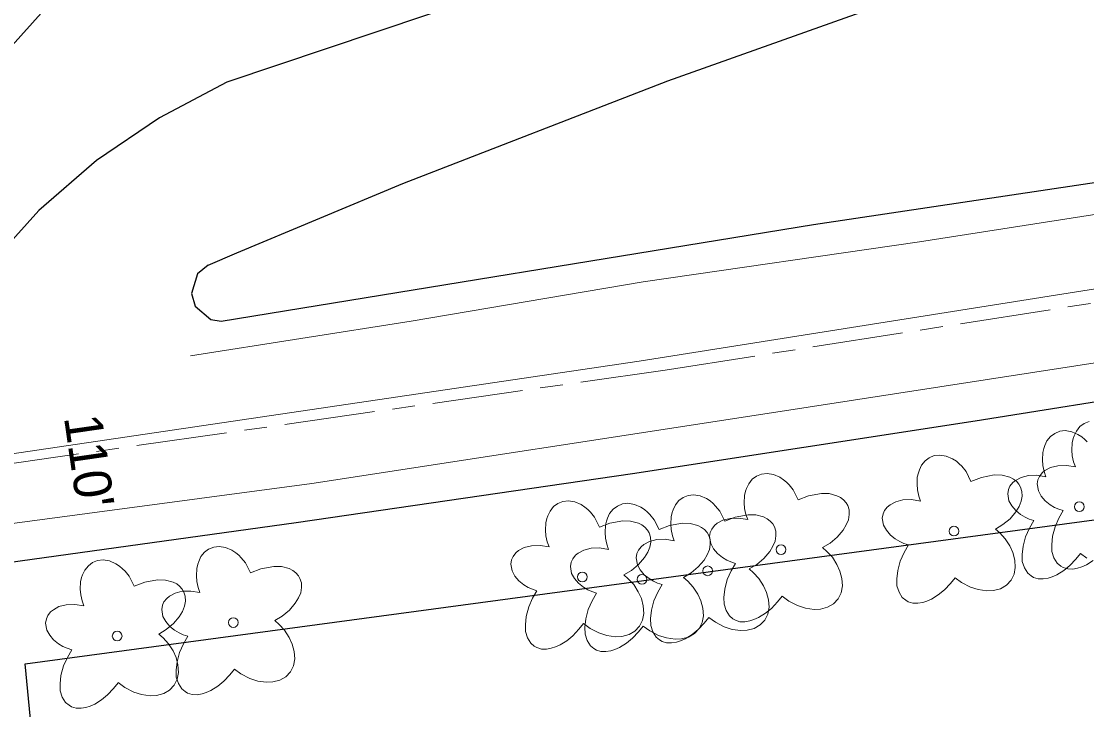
# Model space of a CAD drawing. Extents: x -861682 to -858969, y -1797841 to -1795153.
# Drawn here: x -859343 to -859173.6, y -1796475.1 to -1796365.6 of the extents above; entities that cross this region are included whole.
import ezdxf

# ---------------------------------------------------------------- set-up
doc = ezdxf.new("R2010")
doc.units = 0
doc.header["$LTSCALE"] = 2.4
doc.linetypes.add('LONG_DASH_SHORT_DASH', pattern=[9.9, 6, -1.2, 1.5, -1.2])
for name, color, linetype, lineweight in [('10', 7, 'Continuous', 25), ('17', 7, 'Continuous', 13), ('18', 7, 'Continuous', 13), ('32', 7, 'LONG_DASH_SHORT_DASH', 13), ('42', 7, 'Continuous', 25), ('54', 7, 'Continuous', 13)]:
    doc.layers.add(name, color=color, linetype=linetype, lineweight=lineweight)
doc.layers.add('43', color=7, linetype='Continuous')

msp = doc.modelspace()

# ---------------------------------------------------------------- linework, layer by layer
at = {"layer": '10'}
for points in [[(-859194.317, -1796336.227), (-859199.045, -1796337.856), (-859206.902, -1796340.557), (-859310.306, -1796375.338)], [(-859313.301, -1796404.44), (-859308.712, -1796402.455), (-859282.34, -1796391.428), (-859240.21, -1796375.108), (-859208.017, -1796363.681), (-859179.756, -1796354.374)], [(-859311.205, -1796413.342), (-859217.078, -1796397.962), (-859001.666, -1796365.735)], [(-859310.306, -1796375.338), (-859321.024, -1796380.988), (-859331.034, -1796387.814), (-859340.207, -1796395.728), (-859349.998, -1796406.585), (-859352.992, -1796410.59)], [(-859313.301, -1796404.44), (-859314.993, -1796405.821), (-859315.943, -1796408.916), (-859315.339, -1796410.971), (-859312.867, -1796413.061), (-859311.205, -1796413.342)], [(-859407.383, -1796460.011), (-859360.399, -1796453.848), (-859299.271, -1796445.38), (-859245.842, -1796437.563), (-859191.381, -1796429.192), (-859160.781, -1796424.311), (-859155.845, -1796423.511)]]:
    msp.add_lwpolyline(points, dxfattribs=at)
at = {"layer": '17'}
for points in [[(-859173.538, -1796432.552), (-859173.95, -1796432.15), (-859174.414, -1796431.75), (-859175.016, -1796431.358), (-859176.02, -1796430.926), (-859177.034, -1796430.756), (-859177.922, -1796430.856), (-859178.722, -1796431.19), (-859179.388, -1796431.676), (-859179.948, -1796432.382), (-859180.298, -1796433.138), (-859180.456, -1796433.576), (-859180.624, -1796434.252), (-859180.676, -1796435.414), (-859180.604, -1796436.312), (-859180.392, -1796437.274), (-859180.108, -1796438.08), (-859181.55, -1796437.848), (-859182.908, -1796437.898), (-859184.066, -1796438.184), (-859184.954, -1796438.682), (-859185.394, -1796439.026), (-859185.828, -1796439.592), (-859186.066, -1796440.126), (-859186.19, -1796440.804), (-859185.988, -1796441.908), (-859185.532, -1796442.72), (-859184.908, -1796443.482), (-859184.13, -1796444.098), (-859183.432, -1796444.522), (-859182.768, -1796444.81), (-859182.04, -1796445.048), (-859182.724, -1796446.26), (-859183.346, -1796447.628), (-859183.742, -1796449.13), (-859183.876, -1796450.464), (-859183.866, -1796451.554), (-859183.532, -1796452.572), (-859183.01, -1796453.418), (-859182.452, -1796453.854), (-859182.066, -1796454.1), (-859181.332, -1796454.324), (-859180.538, -1796454.336), (-859179.768, -1796454.212), (-859179.108, -1796454), (-859178.364, -1796453.678), (-859177.288, -1796452.998), (-859176.326, -1796452.212), (-859175.37, -1796451.194), (-859174.624, -1796450.284)], [(-859173.239, -1796429.289), (-859174.039, -1796429.623), (-859174.705, -1796430.109), (-859175.265, -1796430.815), (-859175.615, -1796431.571), (-859175.773, -1796432.009), (-859175.941, -1796432.685), (-859175.993, -1796433.847), (-859175.921, -1796434.745), (-859175.709, -1796435.707), (-859175.425, -1796436.513), (-859176.867, -1796436.281), (-859178.225, -1796436.331), (-859179.383, -1796436.617), (-859180.271, -1796437.115), (-859180.711, -1796437.459), (-859181.145, -1796438.025), (-859181.383, -1796438.559), (-859181.507, -1796439.237), (-859181.305, -1796440.341), (-859180.849, -1796441.153), (-859180.225, -1796441.915), (-859179.447, -1796442.531), (-859178.749, -1796442.955), (-859178.085, -1796443.243), (-859177.357, -1796443.481), (-859178.041, -1796444.693), (-859178.663, -1796446.061), (-859179.059, -1796447.563), (-859179.193, -1796448.897), (-859179.183, -1796449.987), (-859178.849, -1796451.005), (-859178.327, -1796451.851), (-859177.769, -1796452.287), (-859177.383, -1796452.533), (-859176.649, -1796452.757), (-859175.855, -1796452.769), (-859175.085, -1796452.645), (-859174.425, -1796452.433), (-859173.681, -1796452.111), (-859172.605, -1796451.431)], [(-859194.557, -1796454.151), (-859193.515, -1796454.919), (-859192.109, -1796455.641), (-859190.861, -1796456.047), (-859189.489, -1796456.243), (-859188.471, -1796456.193), (-859187.327, -1796455.903), (-859186.395, -1796455.351), (-859185.655, -1796454.563), (-859185.187, -1796453.605), (-859184.977, -1796452.527), (-859185.081, -1796451.331), (-859185.371, -1796450.159), (-859185.857, -1796449.099), (-859186.579, -1796447.955), (-859187.445, -1796447.035), (-859188.127, -1796446.423), (-859186.945, -1796445.707), (-859185.799, -1796444.759), (-859184.879, -1796443.667), (-859184.357, -1796442.811), (-859184.025, -1796441.997), (-859183.879, -1796441.181), (-859183.919, -1796440.419), (-859184.135, -1796439.739), (-859184.393, -1796439.287), (-859184.813, -1796438.813), (-859185.273, -1796438.459), (-859185.839, -1796438.169), (-859187.075, -1796437.841), (-859188.317, -1796437.807), (-859190.363, -1796438.183), (-859192.023, -1796438.821), (-859192.813, -1796437.243), (-859193.467, -1796436.429), (-859193.879, -1796436.027), (-859194.343, -1796435.627), (-859194.945, -1796435.235), (-859195.949, -1796434.803), (-859196.963, -1796434.633), (-859197.851, -1796434.733), (-859198.651, -1796435.067), (-859199.317, -1796435.553), (-859199.877, -1796436.259), (-859200.227, -1796437.015), (-859200.385, -1796437.453), (-859200.553, -1796438.129), (-859200.605, -1796439.291), (-859200.533, -1796440.189), (-859200.321, -1796441.151), (-859200.037, -1796441.957), (-859201.479, -1796441.725), (-859202.837, -1796441.775), (-859203.995, -1796442.061), (-859204.883, -1796442.559), (-859205.323, -1796442.903), (-859205.757, -1796443.469), (-859205.995, -1796444.003), (-859206.119, -1796444.681), (-859205.917, -1796445.785), (-859205.461, -1796446.597), (-859204.837, -1796447.359), (-859204.059, -1796447.975), (-859203.361, -1796448.399), (-859202.697, -1796448.687), (-859201.969, -1796448.925), (-859202.653, -1796450.137), (-859203.275, -1796451.505), (-859203.671, -1796453.007), (-859203.805, -1796454.341), (-859203.795, -1796455.431), (-859203.461, -1796456.449), (-859202.939, -1796457.295), (-859202.381, -1796457.731), (-859201.995, -1796457.977), (-859201.261, -1796458.201), (-859200.467, -1796458.213), (-859199.697, -1796458.089), (-859199.037, -1796457.877), (-859198.293, -1796457.555), (-859197.217, -1796456.875), (-859196.255, -1796456.089), (-859195.299, -1796455.071), (-859194.553, -1796454.161)], [(-859222.041, -1796457.089), (-859220.999, -1796457.857), (-859219.593, -1796458.579), (-859218.345, -1796458.985), (-859216.973, -1796459.181), (-859215.955, -1796459.131), (-859214.811, -1796458.841), (-859213.879, -1796458.289), (-859213.139, -1796457.501), (-859212.671, -1796456.543), (-859212.461, -1796455.465), (-859212.565, -1796454.269), (-859212.855, -1796453.097), (-859213.341, -1796452.037), (-859214.063, -1796450.893), (-859214.929, -1796449.973), (-859215.611, -1796449.361), (-859214.429, -1796448.645), (-859213.283, -1796447.697), (-859212.363, -1796446.605), (-859211.841, -1796445.749), (-859211.509, -1796444.935), (-859211.363, -1796444.119), (-859211.403, -1796443.357), (-859211.619, -1796442.677), (-859211.877, -1796442.225), (-859212.297, -1796441.751), (-859212.757, -1796441.397), (-859213.323, -1796441.107), (-859214.559, -1796440.779), (-859215.801, -1796440.745), (-859217.847, -1796441.121), (-859219.507, -1796441.759), (-859220.297, -1796440.181), (-859220.951, -1796439.367), (-859221.363, -1796438.965), (-859221.827, -1796438.565), (-859222.429, -1796438.173), (-859223.433, -1796437.741), (-859224.447, -1796437.571), (-859225.335, -1796437.671), (-859226.135, -1796438.005), (-859226.801, -1796438.491), (-859227.361, -1796439.197), (-859227.711, -1796439.953), (-859227.869, -1796440.391), (-859228.037, -1796441.067), (-859228.089, -1796442.229), (-859228.017, -1796443.127), (-859227.805, -1796444.089), (-859227.521, -1796444.895), (-859228.963, -1796444.663), (-859230.321, -1796444.713), (-859231.479, -1796444.999), (-859232.367, -1796445.497), (-859232.807, -1796445.841), (-859233.241, -1796446.407), (-859233.479, -1796446.941), (-859233.603, -1796447.619), (-859233.401, -1796448.723), (-859232.945, -1796449.535), (-859232.321, -1796450.297), (-859231.543, -1796450.913), (-859230.845, -1796451.337), (-859230.181, -1796451.625), (-859229.453, -1796451.863), (-859230.137, -1796453.075), (-859230.759, -1796454.443), (-859231.155, -1796455.945), (-859231.289, -1796457.279), (-859231.279, -1796458.369), (-859230.945, -1796459.387), (-859230.423, -1796460.233), (-859229.865, -1796460.669), (-859229.479, -1796460.915), (-859228.745, -1796461.139), (-859227.951, -1796461.151), (-859227.181, -1796461.027), (-859226.521, -1796460.815), (-859225.777, -1796460.493), (-859224.701, -1796459.813), (-859223.739, -1796459.027), (-859222.783, -1796458.009), (-859222.037, -1796457.099)], [(-859233.7, -1796460.467), (-859232.658, -1796461.235), (-859231.252, -1796461.957), (-859230.004, -1796462.363), (-859228.632, -1796462.559), (-859227.614, -1796462.509), (-859226.47, -1796462.219), (-859225.538, -1796461.667), (-859224.798, -1796460.879), (-859224.33, -1796459.921), (-859224.12, -1796458.843), (-859224.224, -1796457.647), (-859224.514, -1796456.475), (-859225, -1796455.415), (-859225.722, -1796454.271), (-859226.588, -1796453.351), (-859227.27, -1796452.739), (-859226.088, -1796452.023), (-859224.942, -1796451.075), (-859224.022, -1796449.983), (-859223.5, -1796449.127), (-859223.168, -1796448.313), (-859223.022, -1796447.497), (-859223.062, -1796446.735), (-859223.278, -1796446.055), (-859223.536, -1796445.603), (-859223.956, -1796445.129), (-859224.416, -1796444.775), (-859224.982, -1796444.485), (-859226.218, -1796444.157), (-859227.46, -1796444.123), (-859229.506, -1796444.499), (-859231.166, -1796445.137), (-859231.956, -1796443.559), (-859232.61, -1796442.745), (-859233.022, -1796442.343), (-859233.486, -1796441.943), (-859234.088, -1796441.551), (-859235.092, -1796441.119), (-859236.106, -1796440.949), (-859236.994, -1796441.049), (-859237.794, -1796441.383), (-859238.46, -1796441.869), (-859239.02, -1796442.575), (-859239.37, -1796443.331), (-859239.528, -1796443.769), (-859239.696, -1796444.445), (-859239.748, -1796445.607), (-859239.676, -1796446.505), (-859239.464, -1796447.467), (-859239.18, -1796448.273), (-859240.622, -1796448.041), (-859241.98, -1796448.091), (-859243.138, -1796448.377), (-859244.026, -1796448.875), (-859244.466, -1796449.219), (-859244.9, -1796449.785), (-859245.138, -1796450.319), (-859245.262, -1796450.997), (-859245.06, -1796452.101), (-859244.604, -1796452.913), (-859243.98, -1796453.675), (-859243.202, -1796454.291), (-859242.504, -1796454.715), (-859241.84, -1796455.003), (-859241.112, -1796455.241), (-859241.796, -1796456.453), (-859242.418, -1796457.821), (-859242.814, -1796459.323), (-859242.948, -1796460.657), (-859242.938, -1796461.747), (-859242.604, -1796462.765), (-859242.082, -1796463.611), (-859241.524, -1796464.047), (-859241.138, -1796464.293), (-859240.404, -1796464.517), (-859239.61, -1796464.529), (-859238.84, -1796464.405), (-859238.18, -1796464.193), (-859237.436, -1796463.871), (-859236.36, -1796463.191), (-859235.398, -1796462.405), (-859234.442, -1796461.387), (-859233.696, -1796460.477)], [(-859253.61, -1796461.438), (-859252.568, -1796462.206), (-859251.162, -1796462.928), (-859249.914, -1796463.334), (-859248.542, -1796463.53), (-859247.524, -1796463.48), (-859246.38, -1796463.19), (-859245.448, -1796462.638), (-859244.708, -1796461.85), (-859244.24, -1796460.892), (-859244.03, -1796459.814), (-859244.134, -1796458.618), (-859244.424, -1796457.446), (-859244.91, -1796456.386), (-859245.632, -1796455.242), (-859246.498, -1796454.322), (-859247.18, -1796453.71), (-859245.998, -1796452.994), (-859244.852, -1796452.046), (-859243.932, -1796450.954), (-859243.41, -1796450.098), (-859243.078, -1796449.284), (-859242.932, -1796448.468), (-859242.972, -1796447.706), (-859243.188, -1796447.026), (-859243.446, -1796446.574), (-859243.866, -1796446.1), (-859244.326, -1796445.746), (-859244.892, -1796445.456), (-859246.128, -1796445.128), (-859247.37, -1796445.094), (-859249.416, -1796445.47), (-859251.076, -1796446.108), (-859251.866, -1796444.53), (-859252.52, -1796443.716), (-859252.932, -1796443.314), (-859253.396, -1796442.914), (-859253.998, -1796442.522), (-859255.002, -1796442.09), (-859256.016, -1796441.92), (-859256.904, -1796442.02), (-859257.704, -1796442.354), (-859258.37, -1796442.84), (-859258.93, -1796443.546), (-859259.28, -1796444.302), (-859259.438, -1796444.74), (-859259.606, -1796445.416), (-859259.658, -1796446.578), (-859259.586, -1796447.476), (-859259.374, -1796448.438), (-859259.09, -1796449.244), (-859260.532, -1796449.012), (-859261.89, -1796449.062), (-859263.048, -1796449.348), (-859263.936, -1796449.846), (-859264.376, -1796450.19), (-859264.81, -1796450.756), (-859265.048, -1796451.29), (-859265.172, -1796451.968), (-859264.97, -1796453.072), (-859264.514, -1796453.884), (-859263.89, -1796454.646), (-859263.112, -1796455.262), (-859262.414, -1796455.686), (-859261.75, -1796455.974), (-859261.022, -1796456.212), (-859261.706, -1796457.424), (-859262.328, -1796458.792), (-859262.724, -1796460.294), (-859262.858, -1796461.628), (-859262.848, -1796462.718), (-859262.514, -1796463.736), (-859261.992, -1796464.582), (-859261.434, -1796465.018), (-859261.048, -1796465.264), (-859260.314, -1796465.488), (-859259.52, -1796465.5), (-859258.75, -1796465.376), (-859258.09, -1796465.164), (-859257.346, -1796464.842), (-859256.27, -1796464.162), (-859255.308, -1796463.376), (-859254.352, -1796462.358), (-859253.606, -1796461.448)], [(-859244.139, -1796461.831), (-859243.097, -1796462.599), (-859241.691, -1796463.321), (-859240.443, -1796463.727), (-859239.071, -1796463.923), (-859238.053, -1796463.873), (-859236.909, -1796463.583), (-859235.977, -1796463.031), (-859235.237, -1796462.243), (-859234.769, -1796461.285), (-859234.559, -1796460.207), (-859234.663, -1796459.011), (-859234.953, -1796457.839), (-859235.439, -1796456.779), (-859236.161, -1796455.635), (-859237.027, -1796454.715), (-859237.709, -1796454.103), (-859236.527, -1796453.387), (-859235.381, -1796452.439), (-859234.461, -1796451.347), (-859233.939, -1796450.491), (-859233.607, -1796449.677), (-859233.461, -1796448.861), (-859233.501, -1796448.099), (-859233.717, -1796447.419), (-859233.975, -1796446.967), (-859234.395, -1796446.493), (-859234.855, -1796446.139), (-859235.421, -1796445.849), (-859236.657, -1796445.521), (-859237.899, -1796445.487), (-859239.945, -1796445.863), (-859241.605, -1796446.501), (-859242.395, -1796444.923), (-859243.049, -1796444.109), (-859243.461, -1796443.707), (-859243.925, -1796443.307), (-859244.527, -1796442.915), (-859245.531, -1796442.483), (-859246.545, -1796442.313), (-859247.433, -1796442.413), (-859248.233, -1796442.747), (-859248.899, -1796443.233), (-859249.459, -1796443.939), (-859249.809, -1796444.695), (-859249.967, -1796445.133), (-859250.135, -1796445.809), (-859250.187, -1796446.971), (-859250.115, -1796447.869), (-859249.903, -1796448.831), (-859249.619, -1796449.637), (-859251.061, -1796449.405), (-859252.419, -1796449.455), (-859253.577, -1796449.741), (-859254.465, -1796450.239), (-859254.905, -1796450.583), (-859255.339, -1796451.149), (-859255.577, -1796451.683), (-859255.701, -1796452.361), (-859255.499, -1796453.465), (-859255.043, -1796454.277), (-859254.419, -1796455.039), (-859253.641, -1796455.655), (-859252.943, -1796456.079), (-859252.279, -1796456.367), (-859251.551, -1796456.605), (-859252.235, -1796457.817), (-859252.857, -1796459.185), (-859253.253, -1796460.687), (-859253.387, -1796462.021), (-859253.377, -1796463.111), (-859253.043, -1796464.129), (-859252.521, -1796464.975), (-859251.963, -1796465.411), (-859251.577, -1796465.657), (-859250.843, -1796465.881), (-859250.049, -1796465.893), (-859249.279, -1796465.769), (-859248.619, -1796465.557), (-859247.875, -1796465.235), (-859246.799, -1796464.555), (-859245.837, -1796463.769), (-859244.881, -1796462.751), (-859244.135, -1796461.841)], [(-859309.106, -1796468.689), (-859308.064, -1796469.457), (-859306.658, -1796470.179), (-859305.41, -1796470.585), (-859304.038, -1796470.781), (-859303.02, -1796470.731), (-859301.876, -1796470.441), (-859300.944, -1796469.889), (-859300.204, -1796469.101), (-859299.736, -1796468.143), (-859299.526, -1796467.065), (-859299.63, -1796465.869), (-859299.92, -1796464.697), (-859300.406, -1796463.637), (-859301.128, -1796462.493), (-859301.994, -1796461.573), (-859302.676, -1796460.961), (-859301.494, -1796460.245), (-859300.348, -1796459.297), (-859299.428, -1796458.205), (-859298.906, -1796457.349), (-859298.574, -1796456.535), (-859298.428, -1796455.719), (-859298.468, -1796454.957), (-859298.684, -1796454.277), (-859298.942, -1796453.825), (-859299.362, -1796453.351), (-859299.822, -1796452.997), (-859300.388, -1796452.707), (-859301.624, -1796452.379), (-859302.866, -1796452.345), (-859304.912, -1796452.721), (-859306.572, -1796453.359), (-859307.362, -1796451.781), (-859308.016, -1796450.967), (-859308.428, -1796450.565), (-859308.892, -1796450.165), (-859309.494, -1796449.773), (-859310.498, -1796449.341), (-859311.512, -1796449.171), (-859312.4, -1796449.271), (-859313.2, -1796449.605), (-859313.866, -1796450.091), (-859314.426, -1796450.797), (-859314.776, -1796451.553), (-859314.934, -1796451.991), (-859315.102, -1796452.667), (-859315.154, -1796453.829), (-859315.082, -1796454.727), (-859314.87, -1796455.689), (-859314.586, -1796456.495), (-859316.028, -1796456.263), (-859317.386, -1796456.313), (-859318.544, -1796456.599), (-859319.432, -1796457.097), (-859319.872, -1796457.441), (-859320.306, -1796458.007), (-859320.544, -1796458.541), (-859320.668, -1796459.219), (-859320.466, -1796460.323), (-859320.01, -1796461.135), (-859319.386, -1796461.897), (-859318.608, -1796462.513), (-859317.91, -1796462.937), (-859317.246, -1796463.225), (-859316.518, -1796463.463), (-859317.202, -1796464.675), (-859317.824, -1796466.043), (-859318.22, -1796467.545), (-859318.354, -1796468.879), (-859318.344, -1796469.969), (-859318.01, -1796470.987), (-859317.488, -1796471.833), (-859316.93, -1796472.269), (-859316.544, -1796472.515), (-859315.81, -1796472.739), (-859315.016, -1796472.751), (-859314.246, -1796472.627), (-859313.586, -1796472.415), (-859312.842, -1796472.093), (-859311.766, -1796471.413), (-859310.804, -1796470.627), (-859309.848, -1796469.609), (-859309.102, -1796468.699)], [(-859174.628, -1796450.274), (-859173.586, -1796451.042)], [(-859327.563, -1796470.836), (-859326.521, -1796471.604), (-859325.115, -1796472.326), (-859323.867, -1796472.732), (-859322.495, -1796472.928), (-859321.477, -1796472.878), (-859320.333, -1796472.588), (-859319.401, -1796472.036), (-859318.661, -1796471.248), (-859318.193, -1796470.29), (-859317.983, -1796469.212), (-859318.087, -1796468.016), (-859318.377, -1796466.844), (-859318.863, -1796465.784), (-859319.585, -1796464.64), (-859320.451, -1796463.72), (-859321.133, -1796463.108), (-859319.951, -1796462.392), (-859318.805, -1796461.444), (-859317.885, -1796460.352), (-859317.363, -1796459.496), (-859317.031, -1796458.682), (-859316.885, -1796457.866), (-859316.925, -1796457.104), (-859317.141, -1796456.424), (-859317.399, -1796455.972), (-859317.819, -1796455.498), (-859318.279, -1796455.144), (-859318.845, -1796454.854), (-859320.081, -1796454.526), (-859321.323, -1796454.492), (-859323.369, -1796454.868), (-859325.029, -1796455.506), (-859325.819, -1796453.928), (-859326.473, -1796453.114), (-859326.885, -1796452.712), (-859327.349, -1796452.312), (-859327.951, -1796451.92), (-859328.955, -1796451.488), (-859329.969, -1796451.318), (-859330.857, -1796451.418), (-859331.657, -1796451.752), (-859332.323, -1796452.238), (-859332.883, -1796452.944), (-859333.233, -1796453.7), (-859333.391, -1796454.138), (-859333.559, -1796454.814), (-859333.611, -1796455.976), (-859333.539, -1796456.874), (-859333.327, -1796457.836), (-859333.043, -1796458.642), (-859334.485, -1796458.41), (-859335.843, -1796458.46), (-859337.001, -1796458.746), (-859337.889, -1796459.244), (-859338.329, -1796459.588), (-859338.763, -1796460.154), (-859339.001, -1796460.688), (-859339.125, -1796461.366), (-859338.923, -1796462.47), (-859338.467, -1796463.282), (-859337.843, -1796464.044), (-859337.065, -1796464.66), (-859336.367, -1796465.084), (-859335.703, -1796465.372), (-859334.975, -1796465.61), (-859335.659, -1796466.822), (-859336.281, -1796468.19), (-859336.677, -1796469.692), (-859336.811, -1796471.026), (-859336.801, -1796472.116), (-859336.467, -1796473.134), (-859335.945, -1796473.98), (-859335.387, -1796474.416), (-859335.001, -1796474.662), (-859334.267, -1796474.886), (-859333.473, -1796474.898), (-859332.703, -1796474.774), (-859332.043, -1796474.562), (-859331.299, -1796474.24), (-859330.223, -1796473.56), (-859329.261, -1796472.774), (-859328.305, -1796471.756), (-859327.559, -1796470.846)]]:
    msp.add_lwpolyline(points, dxfattribs=at)
for centre in [(-859174.808, -1796442.862), (-859194.737, -1796446.739), (-859222.221, -1796449.677), (-859233.88, -1796453.055), (-859253.79, -1796454.026), (-859244.319, -1796454.419), (-859309.286, -1796461.277), (-859327.743, -1796463.424)]:
    msp.add_circle(centre, 0.773, dxfattribs=at)
at = {"layer": '18'}
msp.add_lwpolyline([(-859347.215, -1796129.795), (-859321.586, -1796150.045), (-859299.228, -1796169.09), (-859292.462, -1796192.945), (-859295.557, -1796234.584), (-859300.563, -1796261.567), (-859301.495, -1796283.615), (-859305.463, -1796310.868), (-859319.613, -1796338.001), (-859337.091, -1796361.222), (-859367.474, -1796395.166), (-859401.932, -1796399.926), (-859462.09, -1796406.183), (-859502.465, -1796413.666), (-859545.868, -1796417.533)], dxfattribs=at)
at = {"layer": '32'}
msp.add_lwpolyline([(-861651.105, -1796687.844), (-861333.558, -1796608.31), (-860734.009, -1796456.297), (-860402.78, -1796372.876), (-860279.286, -1796339.345), (-860213.04, -1796323.806), (-860166.423, -1796315.627), (-860126.348, -1796310.72), (-860089.545, -1796308.267), (-860056.831, -1796312.356), (-859995.492, -1796331.984), (-859827.834, -1796395.777), (-859764.042, -1796414.588), (-859688.8, -1796435.852), (-859629.915, -1796444.03), (-859562.034, -1796449.756), (-859471.253, -1796448.938), (-859395.193, -1796443.213), (-859240.62, -1796421.131), (-859002.083, -1796383.657)], dxfattribs=at)
at = {"layer": '42'}
msp.add_lwpolyline([(-859634.674, -1796733.987), (-859605.184, -1796673.009), (-859623.78, -1796512.972), (-859440.994, -1796516.569), (-859439.86, -1796496.911), (-859339.579, -1796497.084), (-859342.387, -1796467.857), (-859104.779, -1796435.814)], dxfattribs=at)
at = {"layer": '54'}
for points in [[(-859316.098, -1796418.873), (-859280.993, -1796413.366), (-859244.156, -1796407.091), (-859200.197, -1796400.735), (-859142.824, -1796391.754), (-859077.601, -1796382.042), (-859005.778, -1796370.863), (-859001.771, -1796370.264)], [(-859002.041, -1796381.842), (-859053.45, -1796390.181), (-859156.868, -1796405.745), (-859244.786, -1796419.699), (-859343.381, -1796434.293), (-859400.907, -1796442.299), (-859441.496, -1796446.496), (-859486.409, -1796447.753), (-859546.168, -1796448.733)], [(-859024.666, -1796396.369), (-859086.63, -1796405.988), (-859154.426, -1796417.212), (-859225.106, -1796428.135), (-859296.827, -1796439.137), (-859350.437, -1796446.328), (-859398.709, -1796453.199), (-859433.489, -1796457.311), (-859461.242, -1796459.332), (-859512.74, -1796459.733), (-859545.87, -1796459.101)]]:
    msp.add_lwpolyline(points, dxfattribs=at)

# ---------------------------------------------------------------- texts
at = {"layer": '43'}
msp.add_text("110'", height=6, rotation=278.207, dxfattribs=at).set_placement((-859336.214, -1796428.625))

doc.saveas('drawing.dxf')
